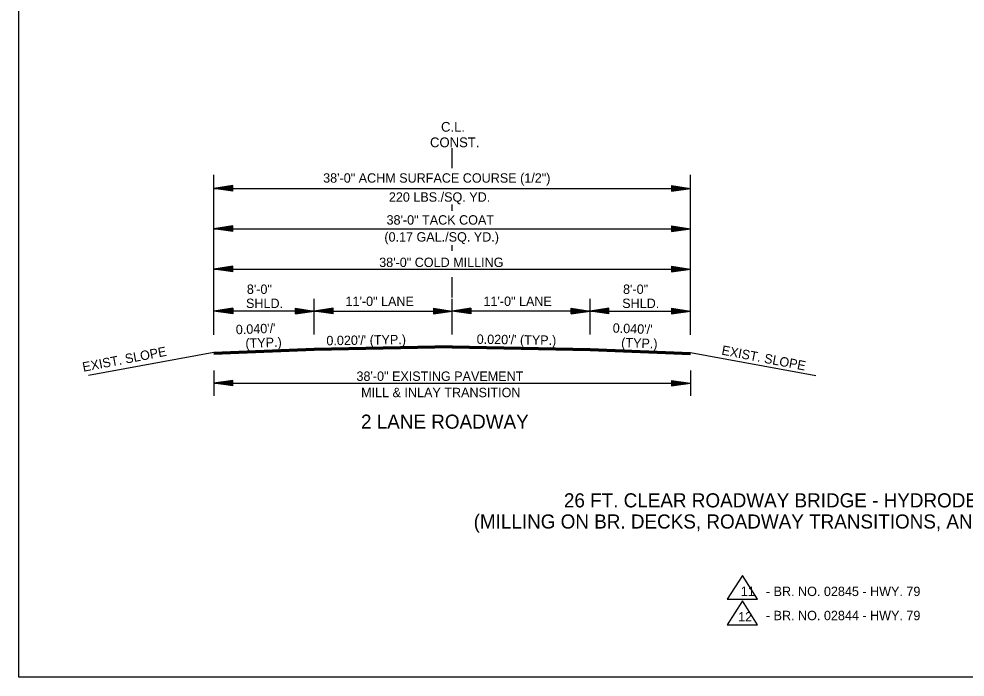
# Model space of a CAD drawing. Extents: x 544199 to 1930787, y -1968972 to 596640.
# Drawn here: x 544199 to 544953, y -1954846 to -1954321 of the extents above; entities that cross this region are included whole.
import ezdxf

# ---------------------------------------------------------------- set-up
doc = ezdxf.new("R2010")
doc.units = 0
for name, color, linetype in [('R_Border', 7, 'Continuous'), ('R_Draft', 7, 'Continuous'), ('R_No Plot', 7, 'Continuous')]:
    doc.layers.add(name, color=color, linetype=linetype)

msp = doc.modelspace()

# ---------------------------------------------------------------- linework, layer by layer
at = {"layer": 'R_Border'}
for p, q in [((544434.43, -1954583.55), (544354.43, -1954586.75)), ((544434.43, -1954583.85), (544354.43, -1954587.05)), ((544434.43, -1954584.15), (544354.43, -1954587.35)), ((544434.43, -1954584.45), (544354.43, -1954587.65)), ((544434.43, -1954584.75), (544354.43, -1954587.95)), ((544434.43, -1954585.05), (544354.43, -1954588.25)), ((544434.43, -1954585.22), (544354.43, -1954588.42)), ((544654.43, -1954583.55), (544734.43, -1954586.75)), ((544654.43, -1954583.85), (544734.43, -1954587.05)), ((544654.43, -1954584.15), (544734.43, -1954587.35)), ((544654.43, -1954584.45), (544734.43, -1954587.65)), ((544654.43, -1954584.75), (544734.43, -1954587.95)), ((544654.43, -1954585.05), (544734.43, -1954588.25)), ((544654.43, -1954585.22), (544734.43, -1954588.42)), ((544775.82, -1954764.61), (544763.68, -1954783.64)), ((544787.97, -1954783.64), (544775.82, -1954764.61)), ((544763.68, -1954783.64), (544787.97, -1954783.64)), ((544775.82, -1954784.91), (544763.68, -1954803.95)), ((544787.97, -1954803.95), (544775.82, -1954784.91)), ((544763.68, -1954803.95), (544787.97, -1954803.95))]:
    msp.add_line(p, q, dxfattribs=at)
at = {"layer": 'R_Draft'}
for p, q in [((544544.43, -1954439.77), (544544.43, -1954423.7)), ((544354.43, -1954572.57), (544354.43, -1954445.08)), ((544734.43, -1954572.57), (544734.43, -1954445.08)), ((544369.43, -1954453.57), (544354.43, -1954455.82)), ((544369.43, -1954453.94), (544356.94, -1954455.82)), ((544369.43, -1954454.32), (544359.52, -1954455.82)), ((544369.43, -1954454.7), (544362.01, -1954455.82)), ((544369.43, -1954458.07), (544369.43, -1954453.57)), ((544719.43, -1954453.57), (544734.43, -1954455.82)), ((544719.43, -1954453.57), (544719.43, -1954458.07)), ((544719.43, -1954453.94), (544731.93, -1954455.82)), ((544719.43, -1954454.32), (544729.35, -1954455.82)), ((544719.43, -1954454.7), (544726.85, -1954455.82)), ((544354.43, -1954455.82), (544734.43, -1954455.82)), ((544369.43, -1954458.07), (544354.43, -1954455.82)), ((544369.43, -1954457.69), (544356.94, -1954455.82)), ((544369.43, -1954457.31), (544359.52, -1954455.82)), ((544369.43, -1954456.93), (544362.01, -1954455.82)), ((544369.43, -1954455.08), (544364.56, -1954455.82)), ((544369.43, -1954456.54), (544364.56, -1954455.82)), ((544369.43, -1954455.46), (544367.06, -1954455.82)), ((544369.43, -1954456.17), (544367.06, -1954455.82)), ((544719.43, -1954455.09), (544724.31, -1954455.82)), ((544719.43, -1954455.46), (544721.8, -1954455.82)), ((544719.43, -1954458.07), (544734.43, -1954455.82)), ((544719.43, -1954456.55), (544724.31, -1954455.82)), ((544719.43, -1954457.31), (544729.35, -1954455.82)), ((544719.43, -1954457.69), (544731.93, -1954455.82)), ((544719.43, -1954456.93), (544726.85, -1954455.82)), ((544719.43, -1954456.17), (544721.8, -1954455.82)), ((544544.43, -1954473.7), (544544.43, -1954468.67)), ((544369.43, -1954485.71), (544354.43, -1954487.96)), ((544354.43, -1954487.96), (544734.43, -1954487.96)), ((544369.43, -1954490.21), (544354.43, -1954487.96)), ((544369.43, -1954486.09), (544356.94, -1954487.96)), ((544369.43, -1954489.84), (544356.94, -1954487.96)), ((544369.43, -1954486.47), (544359.52, -1954487.96)), ((544369.43, -1954489.46), (544359.52, -1954487.96)), ((544369.43, -1954486.85), (544362.01, -1954487.96)), ((544369.43, -1954489.08), (544362.01, -1954487.96)), ((544369.43, -1954487.23), (544364.56, -1954487.96)), ((544369.43, -1954488.69), (544364.56, -1954487.96)), ((544369.43, -1954487.61), (544367.06, -1954487.96)), ((544369.43, -1954488.32), (544367.06, -1954487.96)), ((544369.43, -1954490.21), (544369.43, -1954485.71)), ((544719.43, -1954485.71), (544734.43, -1954487.96)), ((544719.43, -1954485.71), (544719.43, -1954490.21)), ((544719.43, -1954486.09), (544731.93, -1954487.96)), ((544719.43, -1954486.47), (544729.35, -1954487.96)), ((544719.43, -1954486.85), (544726.85, -1954487.96)), ((544719.43, -1954487.24), (544724.31, -1954487.96)), ((544719.43, -1954487.61), (544721.8, -1954487.96)), ((544719.43, -1954490.21), (544734.43, -1954487.96)), ((544719.43, -1954488.7), (544724.31, -1954487.96)), ((544719.43, -1954489.46), (544729.35, -1954487.96)), ((544719.43, -1954489.84), (544731.93, -1954487.96)), ((544719.43, -1954489.08), (544726.85, -1954487.96)), ((544719.43, -1954488.32), (544721.8, -1954487.96)), ((544544.43, -1954505.55), (544544.43, -1954501.1)), ((544369.43, -1954517.95), (544354.43, -1954520.2)), ((544354.43, -1954520.2), (544734.43, -1954520.2)), ((544369.43, -1954522.45), (544354.43, -1954520.2)), ((544369.43, -1954518.33), (544356.94, -1954520.2)), ((544369.43, -1954522.08), (544356.94, -1954520.2)), ((544369.43, -1954518.71), (544359.52, -1954520.2)), ((544369.43, -1954521.7), (544359.52, -1954520.2)), ((544369.43, -1954519.09), (544362.01, -1954520.2)), ((544369.43, -1954521.32), (544362.01, -1954520.2)), ((544369.43, -1954519.47), (544364.56, -1954520.2)), ((544369.43, -1954520.93), (544364.56, -1954520.2)), ((544369.43, -1954519.85), (544367.06, -1954520.2)), ((544369.43, -1954520.56), (544367.06, -1954520.2)), ((544369.43, -1954522.45), (544369.43, -1954517.95)), ((544719.43, -1954517.95), (544734.43, -1954520.2)), ((544719.43, -1954517.95), (544719.43, -1954522.45)), ((544719.43, -1954518.33), (544731.93, -1954520.2)), ((544719.43, -1954518.71), (544729.35, -1954520.2)), ((544719.43, -1954519.09), (544726.85, -1954520.2)), ((544719.43, -1954519.48), (544724.31, -1954520.2)), ((544719.43, -1954519.85), (544721.8, -1954520.2)), ((544719.43, -1954522.45), (544734.43, -1954520.2)), ((544719.43, -1954520.94), (544724.31, -1954520.2)), ((544719.43, -1954521.7), (544729.35, -1954520.2)), ((544719.43, -1954522.08), (544731.93, -1954520.2)), ((544719.43, -1954521.32), (544726.85, -1954520.2)), ((544719.43, -1954520.56), (544721.8, -1954520.2)), ((544544.43, -1954542.97), (544544.43, -1954526.7)), ((544434.43, -1954572.4), (544434.43, -1954543.85)), ((544544.43, -1954572.4), (544544.43, -1954543.85)), ((544654.43, -1954572.4), (544654.43, -1954543.85)), ((544369.43, -1954551.49), (544354.43, -1954553.74)), ((544369.43, -1954551.86), (544356.94, -1954553.74)), ((544369.43, -1954552.25), (544359.52, -1954553.74)), ((544369.43, -1954552.62), (544362.01, -1954553.74)), ((544369.43, -1954551.49), (544369.43, -1954555.99)), ((544419.43, -1954551.49), (544434.43, -1954553.74)), ((544419.43, -1954555.99), (544419.43, -1954551.49)), ((544419.43, -1954551.86), (544431.93, -1954553.74)), ((544419.43, -1954552.25), (544429.35, -1954553.74)), ((544419.43, -1954552.62), (544426.85, -1954553.74)), ((544449.43, -1954551.49), (544434.43, -1954553.74)), ((544449.43, -1954551.86), (544436.94, -1954553.74)), ((544449.43, -1954552.25), (544439.52, -1954553.74)), ((544449.43, -1954552.62), (544442.01, -1954553.74)), ((544449.43, -1954555.99), (544449.43, -1954551.49)), ((544529.43, -1954551.49), (544544.43, -1954553.74)), ((544529.43, -1954551.49), (544529.43, -1954555.99)), ((544529.43, -1954551.86), (544541.93, -1954553.74)), ((544529.43, -1954552.25), (544539.35, -1954553.74)), ((544529.43, -1954552.62), (544536.85, -1954553.74)), ((544559.43, -1954551.49), (544544.43, -1954553.74)), ((544559.43, -1954551.86), (544546.94, -1954553.74)), ((544559.43, -1954552.25), (544549.52, -1954553.74)), ((544559.43, -1954552.62), (544552.01, -1954553.74)), ((544559.43, -1954551.49), (544559.43, -1954555.99)), ((544639.43, -1954551.49), (544654.43, -1954553.74)), ((544639.43, -1954555.99), (544639.43, -1954551.49)), ((544639.43, -1954551.86), (544651.93, -1954553.74)), ((544639.43, -1954552.25), (544649.35, -1954553.74)), ((544639.43, -1954552.62), (544646.85, -1954553.74)), ((544669.43, -1954551.49), (544654.43, -1954553.74)), ((544669.43, -1954551.86), (544656.94, -1954553.74)), ((544669.43, -1954552.25), (544659.52, -1954553.74)), ((544669.43, -1954552.62), (544662.01, -1954553.74)), ((544669.43, -1954555.99), (544669.43, -1954551.49)), ((544719.43, -1954551.49), (544734.43, -1954553.74)), ((544719.43, -1954551.49), (544719.43, -1954555.99)), ((544719.43, -1954551.86), (544731.93, -1954553.74)), ((544719.43, -1954552.25), (544729.35, -1954553.74)), ((544719.43, -1954552.62), (544726.85, -1954553.74)), ((544434.43, -1954553.74), (544354.43, -1954553.74)), ((544369.43, -1954555.99), (544354.43, -1954553.74)), ((544369.43, -1954555.61), (544356.94, -1954553.74)), ((544369.43, -1954555.23), (544359.52, -1954553.74)), ((544369.43, -1954554.86), (544362.01, -1954553.74)), ((544369.43, -1954553.01), (544364.56, -1954553.74)), ((544369.43, -1954554.47), (544364.56, -1954553.74)), ((544369.43, -1954553.39), (544367.06, -1954553.74)), ((544369.43, -1954554.09), (544367.06, -1954553.74)), ((544419.43, -1954553), (544424.31, -1954553.74)), ((544419.43, -1954553.39), (544421.8, -1954553.74)), ((544419.43, -1954555.99), (544434.43, -1954553.74)), ((544419.43, -1954554.47), (544424.31, -1954553.74)), ((544419.43, -1954555.23), (544429.35, -1954553.74)), ((544419.43, -1954555.61), (544431.93, -1954553.74)), ((544419.43, -1954554.86), (544426.85, -1954553.74)), ((544419.43, -1954554.09), (544421.8, -1954553.74)), ((544449.43, -1954555.99), (544434.43, -1954553.74)), ((544434.43, -1954553.74), (544544.43, -1954553.74)), ((544449.43, -1954555.61), (544436.94, -1954553.74)), ((544449.43, -1954555.23), (544439.52, -1954553.74)), ((544449.43, -1954554.86), (544442.01, -1954553.74)), ((544449.43, -1954553), (544444.56, -1954553.74)), ((544449.43, -1954554.47), (544444.56, -1954553.74)), ((544449.43, -1954553.39), (544447.06, -1954553.74)), ((544449.43, -1954554.09), (544447.06, -1954553.74)), ((544529.43, -1954553.01), (544534.31, -1954553.74)), ((544529.43, -1954553.39), (544531.8, -1954553.74)), ((544529.43, -1954555.99), (544544.43, -1954553.74)), ((544529.43, -1954554.47), (544534.31, -1954553.74)), ((544529.43, -1954555.23), (544539.35, -1954553.74)), ((544529.43, -1954555.61), (544541.93, -1954553.74)), ((544529.43, -1954554.86), (544536.85, -1954553.74)), ((544529.43, -1954554.09), (544531.8, -1954553.74)), ((544654.43, -1954553.74), (544544.43, -1954553.74)), ((544559.43, -1954555.99), (544544.43, -1954553.74)), ((544559.43, -1954555.61), (544546.94, -1954553.74)), ((544559.43, -1954555.23), (544549.52, -1954553.74)), ((544559.43, -1954554.86), (544552.01, -1954553.74)), ((544559.43, -1954553.01), (544554.56, -1954553.74)), ((544559.43, -1954554.47), (544554.56, -1954553.74)), ((544559.43, -1954553.39), (544557.06, -1954553.74)), ((544559.43, -1954554.09), (544557.06, -1954553.74)), ((544639.43, -1954553), (544644.31, -1954553.74)), ((544639.43, -1954553.39), (544641.8, -1954553.74)), ((544639.43, -1954555.99), (544654.43, -1954553.74)), ((544639.43, -1954554.47), (544644.31, -1954553.74)), ((544639.43, -1954555.23), (544649.35, -1954553.74)), ((544639.43, -1954555.61), (544651.93, -1954553.74)), ((544639.43, -1954554.86), (544646.85, -1954553.74)), ((544639.43, -1954554.09), (544641.8, -1954553.74)), ((544654.43, -1954553.74), (544734.43, -1954553.74)), ((544669.43, -1954555.99), (544654.43, -1954553.74)), ((544669.43, -1954555.61), (544656.94, -1954553.74)), ((544669.43, -1954555.23), (544659.52, -1954553.74)), ((544669.43, -1954554.86), (544662.01, -1954553.74)), ((544669.43, -1954553), (544664.56, -1954553.74)), ((544669.43, -1954554.47), (544664.56, -1954553.74)), ((544669.43, -1954553.39), (544667.06, -1954553.74)), ((544669.43, -1954554.09), (544667.06, -1954553.74)), ((544719.43, -1954553.01), (544724.31, -1954553.74)), ((544719.43, -1954553.39), (544721.8, -1954553.74)), ((544719.43, -1954555.99), (544734.43, -1954553.74)), ((544719.43, -1954554.47), (544724.31, -1954553.74)), ((544719.43, -1954555.23), (544729.35, -1954553.74)), ((544719.43, -1954555.61), (544731.93, -1954553.74)), ((544719.43, -1954554.86), (544726.85, -1954553.74)), ((544719.43, -1954554.09), (544721.8, -1954553.74)), ((544544.43, -1954581.35), (544434.43, -1954583.55)), ((544544.42, -1954581.65), (544434.43, -1954583.85)), ((544544.43, -1954581.95), (544434.43, -1954584.15)), ((544544.45, -1954582.25), (544434.43, -1954584.45)), ((544544.45, -1954582.55), (544434.43, -1954584.75)), ((544544.46, -1954582.85), (544434.43, -1954585.05)), ((544544.46, -1954583.02), (544434.43, -1954585.22)), ((544544.4, -1954582.85), (544654.43, -1954585.05)), ((544544.4, -1954583.02), (544654.43, -1954585.22)), ((544544.41, -1954582.25), (544654.43, -1954584.45)), ((544544.41, -1954582.55), (544654.43, -1954584.75)), ((544544.42, -1954581.65), (544654.43, -1954583.85)), ((544544.42, -1954581.95), (544654.43, -1954584.15)), ((544544.43, -1954581.35), (544654.43, -1954583.55)), ((544354.43, -1954586.75), (544254.36, -1954605.12)), ((544734.43, -1954586.75), (544834.5, -1954605.12)), ((544354.43, -1954601.2), (544354.43, -1954621.2)), ((544734.43, -1954601.2), (544734.43, -1954621.2)), ((544369.43, -1954608.95), (544354.43, -1954611.2)), ((544354.43, -1954611.2), (544734.43, -1954611.2)), ((544369.43, -1954613.45), (544354.43, -1954611.2)), ((544369.43, -1954609.33), (544356.94, -1954611.2)), ((544369.43, -1954613.08), (544356.94, -1954611.2)), ((544369.43, -1954609.71), (544359.52, -1954611.2)), ((544369.43, -1954612.7), (544359.52, -1954611.2)), ((544369.43, -1954610.09), (544362.01, -1954611.2)), ((544369.43, -1954612.32), (544362.01, -1954611.2)), ((544369.43, -1954610.47), (544364.56, -1954611.2)), ((544369.43, -1954611.93), (544364.56, -1954611.2)), ((544369.43, -1954610.85), (544367.06, -1954611.2)), ((544369.43, -1954611.56), (544367.06, -1954611.2)), ((544369.43, -1954613.45), (544369.43, -1954608.95)), ((544719.43, -1954608.95), (544734.43, -1954611.2)), ((544719.43, -1954608.95), (544719.43, -1954613.45)), ((544719.43, -1954609.33), (544731.93, -1954611.2)), ((544719.43, -1954609.71), (544729.35, -1954611.2)), ((544719.43, -1954610.09), (544726.85, -1954611.2)), ((544719.43, -1954610.48), (544724.31, -1954611.2)), ((544719.43, -1954610.85), (544721.8, -1954611.2)), ((544719.43, -1954613.45), (544734.43, -1954611.2)), ((544719.43, -1954611.94), (544724.31, -1954611.2)), ((544719.43, -1954612.7), (544729.35, -1954611.2)), ((544719.43, -1954613.08), (544731.93, -1954611.2)), ((544719.43, -1954612.32), (544726.85, -1954611.2)), ((544719.43, -1954611.56), (544721.8, -1954611.2))]:
    msp.add_line(p, q, dxfattribs=at)
at = {"layer": 'R_No Plot'}
for points in [[(544198.93, -1954331), (544198.93, -1953803.38), (545382.98, -1953803.38), (545382.98, -1953852.78), (545560.58, -1953852.78), (545560.58, -1953870.63), (545578.78, -1953870.63), (545578.78, -1953867.38), (545656.45, -1953867.38)], [(545794.28, -1954331), (545794.28, -1954845.7), (544198.93, -1954845.7), (544198.93, -1954331)]]:
    msp.add_lwpolyline(points, dxfattribs=at)

# ---------------------------------------------------------------- texts
at = {"layer": 'R_Draft'}
for s, height, p in [('C.L.', 7.8, (544535.53, -1954410.6)), ('CONST.', 7.8, (544526.75, -1954422.97)), ('38\'-0" ACHM SURFACE COURSE (1/2")', 7.5, (544441.53, -1954451.24)), ('220 LBS./SQ. YD. ', 7.5, (544493.94, -1954466.42)), ('38\'-0" TACK COAT', 7.5, (544492.08, -1954484.71)), ('(0.17 GAL./SQ. YD.)', 7.5, (544490.34, -1954498.26)), ('38\'-0" COLD MILLING', 7.5, (544486.23, -1954518.53)), ('8\'-0"', 7.5, (544380.7, -1954539.99)), ('8\'-0"', 7.5, (544680.7, -1954539.99)), ('SHLD.', 7.5, (544380.02, -1954551.24)), ('11\'-0" LANE', 7.5, (544459.37, -1954549.61)), ('11\'-0" LANE', 7.5, (544569.37, -1954549.61)), ('SHLD.', 7.5, (544680.02, -1954551.24)), ('38\'-0" EXISTING PAVEMENT', 7.5, (544468.1, -1954609.37)), ('MILL & INLAY TRANSITION', 7.5, (544471.82, -1954622.38)), ('2 LANE ROADWAY', 11.25, (544471.7, -1954647.52)), ('26 FT. CLEAR ROADWAY BRIDGE - HYDRODEMOLITION', 11.25, (544633.52, -1954710.31)), ('(MILLING ON BR. DECKS, ROADWAY TRANSITIONS, AND NEW GUARDRAIL)', 11.25, (544561.55, -1954727.19)), ('11', 7.5, (544774.58, -1954781.05)), ('- BR. NO. 02845 - HWY. 79', 7.5, (544794.62, -1954781.06)), ('12', 7.5, (544772.45, -1954801.35)), ('- BR. NO. 02844 - HWY. 79', 7.5, (544794.62, -1954800.32))]:
    msp.add_text(s, height=height, dxfattribs=at).set_placement(p)
for s, rotation, p in [("0.040'/' ", 2.29061, (544372.03, -1954572.23)), ("0.040'/' ", 357.70939, (544672.33, -1954570.85)), ('(TYP.)', 2.29061, (544379.68, -1954583.18)), ("0.020'/' (TYP.)", 0.87191, (544444.17, -1954581.02)), ("0.020'/' (TYP.)", 359.12809, (544563.93, -1954579.8)), ('(TYP.)', 357.70939, (544679.08, -1954582.38)), ('EXIST. SLOPE', 10.88286, (544250.34, -1954602.14)), ('EXIST. SLOPE', 349.11714, (544758.81, -1954588.34))]:
    msp.add_text(s, height=7.5, rotation=rotation, dxfattribs=at).set_placement(p)

doc.saveas('drawing.dxf')
